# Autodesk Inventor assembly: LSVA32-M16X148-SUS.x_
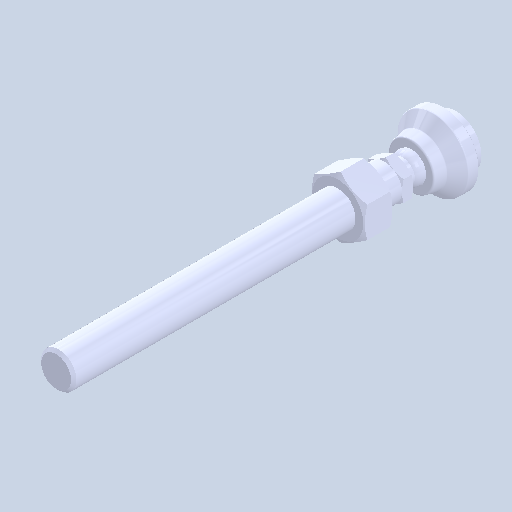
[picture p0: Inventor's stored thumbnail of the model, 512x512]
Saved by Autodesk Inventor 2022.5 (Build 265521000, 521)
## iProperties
Created: 2024-08
Part Number: LSVA32-M16X148-SUS.x_
Document SubType Name: Assembly
Designer: ImaoCorp
Author: ImaoCorp
Sending System: SOLIDWORKS 2022-2022290
MC: AMD64
MC_MODEL: Intel64 Family 6 Model 60 Stepping 3, GenuineIntel
OS: Windows_NT
FRU: Parasolid Version 33.1, build 260,  4-25-2022
FORMAT: text
GUISE: transmit
KEY: FILELSVA32-M16X148-SUS.x_t
DATE: Fri Aug 23 16:06:52 2024
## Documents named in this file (4)
- X:\14_SW2022-Inv2022\06_2024-10新製品(SME)\ELS_データ\l\lsva32-m16x148-sus\LSVA32-M16X148-SUS.x_.iam
- X:\14_SW2022-Inv2022\06_2024-10新製品(SME)\ELS_データ\l\lsva32-m16x148-sus\LSVA32-M16X148-SUS_01.ipt
- X:\14_SW2022-Inv2022\06_2024-10新製品(SME)\ELS_データ\l\lsva32-m16x148-sus\LSVA32-M16X148-SUS_02.ipt
- X:\14_SW2022-Inv2022\06_2024-10新製品(SME)\ELS_データ\l\lsva32-m16x148-sus\LSVA32-M16X148-SUS_03.ipt
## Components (3 placed, 3 different names)
1. LSVA32-M16X148-SUS_01
2. LSVA32-M16X148-SUS_02
3. LSVA32-M16X148-SUS_03
